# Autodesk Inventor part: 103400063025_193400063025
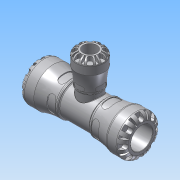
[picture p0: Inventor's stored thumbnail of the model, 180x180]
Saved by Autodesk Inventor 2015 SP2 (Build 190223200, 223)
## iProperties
Created: 2016-12
Part Number: 103400063025_193400063025
Material: PVC-Piping
Description: PLASSON REDUCING TEE 63X25X63 SERIES 1
Document SubType Name: Modeling
Designer: KIM
Mass: 664.223 g
Surface Area: 733.008 cm^2
Volume: 474.445 cm^3
Density: 1.4 g/cm^3
Appearance: Smooth - White
Author: KIM
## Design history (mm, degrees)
derived "1034.ipt"
feature "Solid1::1034.ipt"
tag "TaggingFeature1"
body "Solid1"
other parameters: "d9" = 12.125, "d11" = 103, "d12" = 78.75, "d230" = 47, "d231" = 31.25, "d232" = 7.875, "d1" = 37.8, "d2" = 63, "d3" = 78.75, "d4" = 103, "d8" = 87.55, "d13" = 9.7, "d14" = 9.7, "d15" = 0, "d17" = 360 deg, "d19" = 8 deg, "d20" = 1.26, "d21" = 1.26, "d22" = 8 deg, "d24" = 0, "d26" = 360 deg, "d33" = 10.3, "d43" = 80.34, "d51" = 1.03, "d54" = 22.05, "d55" = 13.86, "d57" = 19.012, "d58" = 0, "d74" = 0, "d77" = 5.25, "d79" = 80.34, "d80" = 262, "d82" = 1.26, "d115" = 360 deg, "d139" = 9.7, "d140" = 0, "d142" = 360 deg, "d207" = 90 deg, "d209" = 20.58, "d210" = 25, "d211" = 31.25, "d212" = 47, "d213" = 39.95, "d215" = 36.66, "d216" = 2.08333, "d217" = 49, "d225" = 96, "d226" = 49, "d228" = 18.7425, "d229" = 6.3, "d233" = 6.3, "d234" = 0, "d236" = 360 deg, "d238" = 8 deg, "d239" = 8 deg, "d240" = 1.26, "d241" = 1.26, "d243" = 0, "d245" = 360 deg, "d247" = 2.06, "d248" = 5.4, "d249" = 2.94, "d250" = 7.4375, "d252" = 8.75, "d253" = 5.75, "d254" = 19.012, "d255" = 0, "d257" = 360 deg, "d259" = 1.26, "d261" = 0, "d262" = 2.06, "d264" = 0, "d266" = 0, "d267" = 1.03, "d_" = 63, "E_" = 103, "A_" = 96, "H_" = 262, "d_1" = 25, "E_1" = 47, "l_1" = 49
